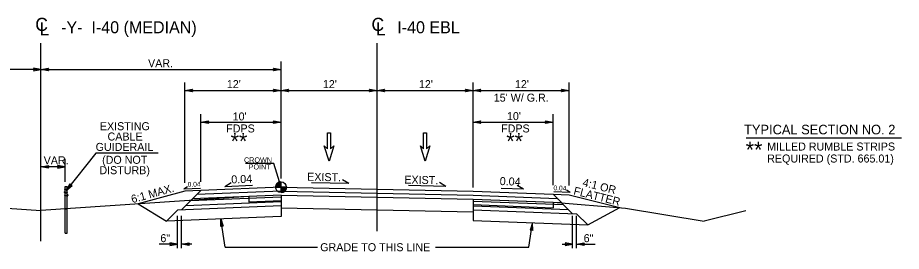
# Model space of a CAD drawing. Extents: x 1553195 to 1553792, y 810516 to 810787.
# Drawn here: x 1553280.5 to 1553390.9, y 810700.2 to 810729.4 of the extents above; entities that cross this region are included whole.
import ezdxf

# ---------------------------------------------------------------- set-up
doc = ezdxf.new("R2010")
doc.units = 0
for name, color, linetype in [('Old_Level_11', 7, 'Continuous'), ('Prop Dimension', 7, 'Continuous'), ('Prop DSN Text', 7, 'Continuous'), ('Prop Pavement Schedule Description CELL', 7, 'Continuous'), ('Prop Shade Light', 7, 'Continuous'), ('Prop Typical Section', 7, 'Continuous'), ('Sheet Sticker Incomplete CELL', 7, 'Continuous'), ('Typical Grade Point Symbol CELL', 7, 'Continuous'), ('Typical Pavement Slope CELL', 7, 'Continuous'), ('Typical Text Centerline CELL', 7, 'Continuous'), ('Typical Text Grade Point CELL', 7, 'Continuous'), ('Typical Text ID Circle CELL', 7, 'Continuous'), ('z - Construction', 7, 'Continuous')]:
    doc.layers.add(name, color=color, linetype=linetype)

msp = doc.modelspace()

# ---------------------------------------------------------------- linework, layer by layer
at = {"layer": 'Old_Level_11'}
for p, q in [((1553312.72, 810708.17), (1553313.39, 810708.17)), ((1553313.39, 810708.17), (1553313.39, 810708.84)), ((1553313.39, 810707.5), (1553313.39, 810708.17)), ((1553314.06, 810708.17), (1553313.39, 810708.17)), ((1553313.39, 810708.17), (1553313.39, 810707.5))]:
    msp.add_line(p, q, dxfattribs=at)
for points in [[(1553312.73, 810708.27), (1553312.73, 810708.17)], [(1553312.74, 810708.34), (1553312.74, 810708.17)], [(1553312.75, 810708.38), (1553312.75, 810708.17)], [(1553312.77, 810708.42), (1553312.77, 810708.17)], [(1553312.78, 810708.45), (1553312.78, 810708.17)], [(1553312.79, 810708.48), (1553312.79, 810708.17)], [(1553312.81, 810708.5), (1553312.81, 810708.17)], [(1553312.82, 810708.53), (1553312.82, 810708.17)], [(1553312.83, 810708.55), (1553312.83, 810708.17)], [(1553312.85, 810708.57), (1553312.85, 810708.17)], [(1553312.86, 810708.58), (1553312.86, 810708.17)], [(1553312.87, 810708.6), (1553312.87, 810708.17)], [(1553312.89, 810708.62), (1553312.89, 810708.17)], [(1553312.9, 810708.63), (1553312.9, 810708.17)], [(1553312.91, 810708.64), (1553312.91, 810708.17)], [(1553312.93, 810708.66), (1553312.93, 810708.17)], [(1553312.94, 810708.67), (1553312.94, 810708.17)], [(1553312.95, 810708.68), (1553312.95, 810708.17)], [(1553312.97, 810708.69), (1553312.97, 810708.17)], [(1553312.98, 810708.7), (1553312.98, 810708.17)], [(1553312.99, 810708.71), (1553312.99, 810708.17)], [(1553313.01, 810708.72), (1553313.01, 810708.17)], [(1553313.02, 810708.73), (1553313.02, 810708.17)], [(1553313.03, 810708.74), (1553313.03, 810708.17)], [(1553313.05, 810708.75), (1553313.05, 810708.17)], [(1553313.06, 810708.76), (1553313.06, 810708.17)], [(1553313.07, 810708.76), (1553313.07, 810708.17)], [(1553313.09, 810708.77), (1553313.09, 810708.17)], [(1553313.1, 810708.78), (1553313.1, 810708.17)], [(1553313.11, 810708.78), (1553313.11, 810708.17)], [(1553313.13, 810708.79), (1553313.13, 810708.17)], [(1553313.14, 810708.8), (1553313.14, 810708.17)], [(1553313.16, 810708.8), (1553313.16, 810708.17)], [(1553313.17, 810708.81), (1553313.17, 810708.17)], [(1553313.18, 810708.81), (1553313.18, 810708.17)], [(1553313.2, 810708.82), (1553313.2, 810708.17)], [(1553313.21, 810708.82), (1553313.21, 810708.17)], [(1553313.22, 810708.82), (1553313.22, 810708.17)], [(1553313.24, 810708.83), (1553313.24, 810708.17)], [(1553313.25, 810708.83), (1553313.25, 810708.17)], [(1553313.26, 810708.83), (1553313.26, 810708.17)], [(1553313.28, 810708.83), (1553313.28, 810708.17)], [(1553313.29, 810708.84), (1553313.29, 810708.17)], [(1553313.3, 810708.84), (1553313.3, 810708.17)], [(1553313.32, 810708.84), (1553313.32, 810708.17)], [(1553313.33, 810708.84), (1553313.33, 810708.17)], [(1553313.34, 810708.84), (1553313.34, 810708.17)], [(1553313.36, 810708.84), (1553313.36, 810708.17)], [(1553313.37, 810708.84), (1553313.37, 810708.17)], [(1553313.38, 810708.84), (1553313.38, 810708.84), (1553313.38, 810708.17)], [(1553313.4, 810708.17), (1553313.4, 810707.5), (1553313.4, 810707.5)], [(1553313.41, 810708.17), (1553313.41, 810707.5)], [(1553313.43, 810708.17), (1553313.43, 810707.5)], [(1553313.44, 810708.17), (1553313.44, 810707.5)], [(1553313.45, 810708.17), (1553313.45, 810707.5)], [(1553313.47, 810708.17), (1553313.47, 810707.51)], [(1553313.48, 810708.17), (1553313.48, 810707.51)], [(1553313.49, 810708.17), (1553313.49, 810707.51)], [(1553313.51, 810708.17), (1553313.51, 810707.51)], [(1553313.52, 810708.17), (1553313.52, 810707.51)], [(1553313.53, 810708.17), (1553313.53, 810707.52)], [(1553313.55, 810708.17), (1553313.55, 810707.52)], [(1553313.56, 810708.17), (1553313.56, 810707.52)], [(1553313.57, 810708.17), (1553313.57, 810707.53)], [(1553313.59, 810708.17), (1553313.59, 810707.53)], [(1553313.6, 810708.17), (1553313.6, 810707.53)], [(1553313.61, 810708.17), (1553313.61, 810707.54)], [(1553313.63, 810708.17), (1553313.63, 810707.54)], [(1553313.64, 810708.17), (1553313.64, 810707.55)], [(1553313.65, 810708.17), (1553313.65, 810707.56)], [(1553313.67, 810708.17), (1553313.67, 810707.56)], [(1553313.68, 810708.17), (1553313.68, 810707.57)], [(1553313.7, 810708.17), (1553313.7, 810707.57)], [(1553313.71, 810708.17), (1553313.71, 810707.58)], [(1553313.72, 810708.17), (1553313.72, 810707.59)], [(1553313.74, 810708.17), (1553313.74, 810707.6)], [(1553313.75, 810708.17), (1553313.75, 810707.61)], [(1553313.76, 810708.17), (1553313.76, 810707.61)], [(1553313.78, 810708.17), (1553313.78, 810707.62)], [(1553313.79, 810708.17), (1553313.79, 810707.63)], [(1553313.8, 810708.17), (1553313.8, 810707.64)], [(1553313.82, 810708.17), (1553313.82, 810707.65)], [(1553313.83, 810708.17), (1553313.83, 810707.66)], [(1553313.84, 810708.17), (1553313.84, 810707.68)], [(1553313.86, 810708.17), (1553313.86, 810707.69)], [(1553313.87, 810708.17), (1553313.87, 810707.7)], [(1553313.88, 810708.17), (1553313.88, 810707.72)], [(1553313.9, 810708.17), (1553313.9, 810707.73)], [(1553313.91, 810708.17), (1553313.91, 810707.75)], [(1553313.92, 810708.17), (1553313.92, 810707.76)], [(1553313.94, 810708.17), (1553313.94, 810707.78)], [(1553313.95, 810708.17), (1553313.95, 810707.8)], [(1553313.96, 810708.17), (1553313.96, 810707.82)], [(1553313.98, 810708.17), (1553313.98, 810707.85)], [(1553313.99, 810708.17), (1553313.99, 810707.87)], [(1553314, 810708.17), (1553314, 810707.9)], [(1553314.02, 810708.17), (1553314.02, 810707.93)], [(1553314.03, 810708.17), (1553314.03, 810707.97)], [(1553314.04, 810708.17), (1553314.04, 810708.02)], [(1553314.06, 810708.17), (1553314.06, 810708.1)]]:
    msp.add_lwpolyline(points, dxfattribs=at)
msp.add_circle((1553313.39, 810708.17), 0.671, dxfattribs=at)
for start, end in [(90.0095, 180.0095), (270.0095, 0.0095)]:
    msp.add_arc((1553313.39, 810708.17), 0.671, start, end, dxfattribs=at)
at = {"layer": 'Prop Dimension'}
for p, q in [((1553301.25, 810707.99), (1553301.71, 810708.28)), ((1553301.25, 810707.99), (1553303.32, 810708.07)), ((1553306.39, 810708.27), (1553307.16, 810708.76)), ((1553306.39, 810708.27), (1553309.84, 810708.41)), ((1553321.86, 810708.64), (1553317.2, 810708.73)), ((1553321.86, 810708.64), (1553321.07, 810709.11)), ((1553333.99, 810708.27), (1553329.33, 810708.37)), ((1553333.99, 810708.27), (1553333.2, 810708.75)), ((1553343.67, 810707.91), (1553340.88, 810708.02)), ((1553343.67, 810707.91), (1553342.9, 810708.4)), ((1553349.53, 810707.51), (1553347.46, 810707.59)), ((1553349.53, 810707.51), (1553349.07, 810707.8))]:
    msp.add_line(p, q, dxfattribs=at)
at = {"layer": 'Prop DSN Text'}
for points in [[(1553282.45, 810722.72), (1553283.39, 810722.88), (1553282.45, 810723.05), (1553282.57, 810722.88)], [(1553284.33, 810722.72), (1553283.39, 810722.88), (1553284.33, 810723.05), (1553284.21, 810722.88)], [(1553312.45, 810723.05), (1553313.39, 810722.88), (1553312.45, 810722.72), (1553312.57, 810722.88)], [(1553302.33, 810720.1), (1553301.39, 810720.26), (1553302.33, 810720.43), (1553302.21, 810720.26)], [(1553312.45, 810720.42), (1553313.39, 810720.26), (1553312.45, 810720.09), (1553312.57, 810720.26)], [(1553314.33, 810720.1), (1553313.39, 810720.26), (1553314.33, 810720.43), (1553314.21, 810720.26)], [(1553324.45, 810720.42), (1553325.39, 810720.26), (1553324.45, 810720.09), (1553324.57, 810720.26)], [(1553326.33, 810720.1), (1553325.39, 810720.26), (1553326.33, 810720.43), (1553326.21, 810720.26)], [(1553336.45, 810720.42), (1553337.39, 810720.26), (1553336.45, 810720.09), (1553336.57, 810720.26)], [(1553338.33, 810720.1), (1553337.39, 810720.26), (1553338.33, 810720.43), (1553338.21, 810720.26)], [(1553348.45, 810720.42), (1553349.39, 810720.26), (1553348.45, 810720.09), (1553348.57, 810720.26)], [(1553304.33, 810716.15), (1553303.39, 810716.31), (1553304.33, 810716.47), (1553304.21, 810716.31)], [(1553312.45, 810716.47), (1553313.39, 810716.31), (1553312.45, 810716.14), (1553312.57, 810716.31)], [(1553338.33, 810716.15), (1553337.39, 810716.31), (1553338.33, 810716.47), (1553338.21, 810716.31)], [(1553346.45, 810716.47), (1553347.39, 810716.31), (1553346.45, 810716.14), (1553346.57, 810716.31)], [(1553284.33, 810710.57), (1553283.39, 810710.73), (1553284.33, 810710.9), (1553284.21, 810710.73)], [(1553285.48, 810710.57), (1553286.41, 810710.73), (1553285.47, 810710.9), (1553285.59, 810710.73)], [(1553287.02, 810708.59), (1553286.57, 810707.76), (1553287.29, 810708.39), (1553287.08, 810708.4)], [(1553305.86, 810703.25), (1553305.88, 810704.2), (1553306.18, 810703.3), (1553306, 810703.39)], [(1553344.85, 810702.78), (1553344.83, 810703.73), (1553344.53, 810702.82), (1553344.71, 810702.91)], [(1553299.52, 810700.89), (1553300.46, 810701.05), (1553299.52, 810701.22), (1553299.64, 810701.05)], [(1553301.9, 810700.89), (1553300.96, 810701.05), (1553301.9, 810701.22), (1553301.78, 810701.05)], [(1553348.88, 810700.89), (1553349.82, 810701.05), (1553348.88, 810701.22), (1553349, 810701.05)], [(1553351.26, 810700.89), (1553350.32, 810701.05), (1553351.26, 810701.22), (1553351.14, 810701.05)]]:
    msp.add_lwpolyline(points, close=True, dxfattribs=at)
at = {"layer": 'Prop Pavement Schedule Description CELL'}
for p, q in [((1553349.39, 810708.4), (1553349.39, 810721.26)), ((1553347.39, 810708.41), (1553347.39, 810717.31)), ((1553371.49, 810714.36), (1553390.89, 810714.36)), ((1553306.41, 810700.67), (1553305.88, 810704.2)), ((1553344.37, 810700.67), (1553344.83, 810703.73)), ((1553306.41, 810700.67), (1553317.97, 810700.67)), ((1553332.69, 810700.67), (1553344.37, 810700.67))]:
    msp.add_line(p, q, dxfattribs=at)
at = {"layer": 'Prop Typical Section'}
for p, q in [((1553283.39, 810701.41), (1553283.39, 810726.17)), ((1553325.39, 810702.69), (1553325.39, 810726.17))]:
    msp.add_line(p, q, dxfattribs=at)
for points in [[(1553318.8, 810713.33), (1553319.2, 810712.96), (1553319.2, 810714.96), (1553319.58, 810714.96), (1553319.58, 810712.96), (1553319.98, 810713.33), (1553319.39, 810711.43)], [(1553318.8, 810713.33), (1553319.2, 810712.96), (1553319.2, 810714.96), (1553319.58, 810714.96), (1553319.58, 810712.96), (1553319.98, 810713.33), (1553319.39, 810711.43)], [(1553330.8, 810713.33), (1553331.2, 810712.96), (1553331.2, 810714.96), (1553331.58, 810714.96), (1553331.58, 810712.96), (1553331.98, 810713.33), (1553331.39, 810711.43)], [(1553330.8, 810713.33), (1553331.2, 810712.96), (1553331.2, 810714.96), (1553331.58, 810714.96), (1553331.58, 810712.96), (1553331.98, 810713.33), (1553331.39, 810711.43)]]:
    msp.add_lwpolyline(points, close=True, dxfattribs=at)
at = {"layer": 'Sheet Sticker Incomplete CELL'}
for p, q in [((1553301.39, 810707.69), (1553295.55, 810706.08)), ((1553303.39, 810707.77), (1553301.39, 810707.69)), ((1553347.39, 810707.29), (1553349.39, 810707.21)), ((1553349.39, 810707.21), (1553355.74, 810705.62)), ((1553295.55, 810706.08), (1553299.07, 810703.93)), ((1553351.71, 810703.45), (1553355.74, 810705.62))]:
    msp.add_line(p, q, dxfattribs=at)
at = {"layer": 'Typical Grade Point Symbol CELL'}
for p, q in [((1553257.39, 810707.01), (1553283.39, 810705.25)), ((1553309.39, 810707.01), (1553283.39, 810705.25)), ((1553313.39, 810707.17), (1553309.39, 810707.01)), ((1553309.39, 810707.01), (1553309.39, 810706.31)), ((1553313.39, 810707.17), (1553325.39, 810706.93)), ((1553313.39, 810707.17), (1553313.39, 810705.59)), ((1553325.39, 810706.93), (1553337.39, 810706.69)), ((1553313.39, 810706.47), (1553309.39, 810706.31)), ((1553337.39, 810706.69), (1553347.39, 810706.29)), ((1553337.39, 810706.69), (1553337.39, 810705.11)), ((1553337.39, 810705.99), (1553347.39, 810705.59)), ((1553347.39, 810706.29), (1553347.39, 810705.59)), ((1553347.39, 810706.29), (1553356.44, 810705.57)), ((1553313.39, 810705.59), (1553325.39, 810705.35)), ((1553325.39, 810705.35), (1553337.39, 810705.11)), ((1553356.44, 810705.57), (1553366.26, 810703.93)), ((1553371.47, 810705.23), (1553366.26, 810703.93))]:
    msp.add_line(p, q, dxfattribs=at)
at = {"layer": 'Typical Pavement Slope CELL'}
for p, q in [((1553313.39, 810708.17), (1553303.39, 810707.77)), ((1553313.39, 810708.17), (1553337.39, 810707.69)), ((1553303.39, 810707.77), (1553300.96, 810705.34)), ((1553313.39, 810706.92), (1553302.09, 810706.47)), ((1553313.39, 810707.17), (1553302.35, 810706.73)), ((1553313.39, 810707.67), (1553302.87, 810707.25)), ((1553313.39, 810707.67), (1553325.39, 810707.43)), ((1553325.39, 810707.43), (1553337.39, 810707.19)), ((1553337.39, 810707.69), (1553347.39, 810707.29)), ((1553337.39, 810707.19), (1553347.91, 810706.77)), ((1553347.39, 810707.29), (1553349.82, 810704.86)), ((1553313.39, 810705.84), (1553300.46, 810705.32)), ((1553313.39, 810706.34), (1553301.48, 810705.86)), ((1553337.39, 810706.69), (1553348.43, 810706.25)), ((1553337.39, 810706.44), (1553348.69, 810705.99)), ((1553337.39, 810705.86), (1553349.3, 810705.38)), ((1553300.46, 810705.32), (1553299.07, 810703.93)), ((1553313.39, 810705.59), (1553313.39, 810704.51)), ((1553337.39, 810705.36), (1553350.32, 810704.84)), ((1553337.39, 810705.11), (1553337.39, 810704.03)), ((1553350.32, 810704.84), (1553351.71, 810703.45)), ((1553313.39, 810704.51), (1553299.07, 810703.93)), ((1553337.39, 810704.03), (1553351.71, 810703.45))]:
    msp.add_line(p, q, dxfattribs=at)
at = {"layer": 'Typical Text Centerline CELL'}
for p, q in [((1553286.41, 810702.42), (1553286.41, 810708.25)), ((1553286.41, 810708.25), (1553286.66, 810708.25)), ((1553286.66, 810702.42), (1553286.66, 810708.25)), ((1553286.67, 810708.01), (1553286.67, 810708.04)), ((1553286.67, 810708.04), (1553286.7, 810708.04)), ((1553286.38, 810707.88), (1553286.38, 810707.91)), ((1553286.38, 810707.91), (1553286.7, 810707.91)), ((1553286.7, 810707.88), (1553286.38, 810707.88)), ((1553286.41, 810707.64), (1553286.38, 810707.64)), ((1553286.38, 810707.62), (1553286.41, 810707.62)), ((1553286.7, 810707.51), (1553286.38, 810707.51)), ((1553286.38, 810707.49), (1553286.7, 810707.49)), ((1553286.38, 810707.09), (1553286.38, 810707.12)), ((1553286.38, 810707.12), (1553286.7, 810707.12)), ((1553286.7, 810707.09), (1553286.38, 810707.09)), ((1553286.41, 810707.62), (1553286.41, 810707.64)), ((1553286.7, 810708.01), (1553286.67, 810708.01)), ((1553286.67, 810707.22), (1553286.67, 810707.25)), ((1553286.67, 810707.25), (1553286.7, 810707.25)), ((1553286.7, 810707.22), (1553286.67, 810707.22)), ((1553286.7, 810707.49), (1553286.7, 810707.51)), ((1553286.41, 810702.42), (1553286.66, 810702.42))]:
    msp.add_line(p, q, dxfattribs=at)
for centre in [(1553286.37, 810707.56), (1553286.71, 810707.96), (1553286.71, 810707.17)]:
    msp.add_circle(centre, 0.0416, dxfattribs=at)
for centre, radius, start, end in [((1553286.7, 810707.96), 0.0781, 270, 90), ((1553286.38, 810707.56), 0.0781, 90, 270), ((1553286.38, 810707.56), 0.0521, 90, 270), ((1553286.7, 810707.96), 0.0521, 270, 90), ((1553286.7, 810707.17), 0.0781, 270, 90), ((1553286.7, 810707.17), 0.0521, 270, 90)]:
    msp.add_arc(centre, radius, start, end, dxfattribs=at)
at = {"layer": 'Typical Text Grade Point CELL'}
msp.add_line((1553286.41, 810705.46), (1553286.66, 810705.46), dxfattribs=at)
at = {"layer": 'Typical Text ID Circle CELL'}
msp.add_lwpolyline([(1553313.39, 810708.17), (1553312.49, 810711.13), (1553308.95, 810711.13)], dxfattribs=at)
at = {"layer": 'z - Construction'}
for p, q in [((1553313.39, 810709.28), (1553313.39, 810723.88)), ((1553283.39, 810722.88), (1553253.39, 810722.88)), ((1553283.39, 810722.88), (1553313.39, 810722.88)), ((1553301.39, 810708.74), (1553301.39, 810721.26)), ((1553301.39, 810720.26), (1553313.39, 810720.26)), ((1553313.39, 810720.26), (1553325.39, 810720.26)), ((1553325.39, 810720.26), (1553337.39, 810720.26)), ((1553337.39, 810708.14), (1553337.39, 810721.26)), ((1553337.39, 810720.26), (1553349.39, 810720.26)), ((1553303.39, 810708.86), (1553303.39, 810717.31)), ((1553303.39, 810716.31), (1553313.39, 810716.31)), ((1553337.39, 810716.31), (1553347.39, 810716.31)), ((1553286.41, 810708.84), (1553286.41, 810711.73)), ((1553286.41, 810710.73), (1553283.39, 810710.73)), ((1553300.46, 810700.57), (1553300.46, 810704.58)), ((1553300.96, 810700.57), (1553300.96, 810704.58)), ((1553349.82, 810700.57), (1553349.82, 810704.58)), ((1553350.32, 810700.57), (1553350.32, 810704.58)), ((1553300.46, 810701.05), (1553298.16, 810701.05)), ((1553302.25, 810701.05), (1553300.96, 810701.05)), ((1553348.53, 810701.05), (1553349.82, 810701.05)), ((1553350.32, 810701.05), (1553352.62, 810701.05))]:
    msp.add_line(p, q, dxfattribs=at)
msp.add_lwpolyline([(1553298.06, 810712.41), (1553290.25, 810712.41), (1553286.57, 810707.76)], dxfattribs=at)

# ---------------------------------------------------------------- texts
at = {"layer": 'Prop Pavement Schedule Description CELL'}
for s, height, p in [('-Y-  I-40 (MEDIAN)', 1.5, (1553285.92, 810727.42)), ('I-40 EBL', 1.5, (1553327.92, 810727.42)), ('VAR.', 1, (1553296.78, 810723.18)), ("12'", 1, (1553306.62, 810720.56)), ("12'", 1, (1553318.62, 810720.56)), ("12'", 1, (1553330.62, 810720.56)), ("12'", 1, (1553342.62, 810720.56)), ("15' W/ G.R.", 1, (1553339.97, 810718.87)), ("10'", 1, (1553307.35, 810716.52)), ("10'", 1, (1553341.62, 810716.56)), ('EXISTING', 1, (1553290.76, 810715.3)), ('FDPS', 1, (1553306.54, 810715.02)), ('FDPS', 1, (1553340.89, 810715.02)), ('TYPICAL SECTION NO. 2', 1.2, (1553371.24, 810714.78)), ('CABLE', 1, (1553291.72, 810714.01)), ('**', 2, (1553307.1, 810712.93)), ('**', 2, (1553341.54, 810712.93)), ('GUIDERAIL', 1, (1553290.23, 810712.71)), ('**', 2, (1553371.45, 810711.86)), ('MILLED RUMBLE STRIPS', 1, (1553374.13, 810712.76)), ('VAR.', 1, (1553283.74, 810711.03)), ('(DO NOT', 1, (1553291.04, 810711.1)), ('REQUIRED (STD. 665.01)', 1, (1553374.13, 810711.26)), ('DISTURB)', 1, (1553290.7, 810709.8)), ('6"', 1, (1553298.32, 810701.3)), ('6"', 1, (1553351.2, 810701.3)), ('GRADE TO THIS LINE', 1, (1553318.29, 810700.17))]:
    msp.add_text(s, height=height, dxfattribs=at).set_placement(p)
for s, height, rotation, p in [('0.04', 1, 2.2906, (1553307.2, 810708.64)), ('EXIST.', 1, 358.8541, (1553316.65, 810708.99)), ('EXIST.', 1, 358.8541, (1553328.79, 810708.63)), ('0.04', 1, 357.7094, (1553340.7, 810708.45)), ('4:1 OR', 1, 345.9638, (1553351, 810708.33)), ('6:1 MAX.', 1, 15.4677, (1553294.82, 810706.17)), ('0.04', 0.6, 2.2906, (1553301.74, 810708.21)), ('0.04', 0.6, 357.7094, (1553347.42, 810707.8)), ('FLATTER', 1, 345.9638, (1553349.87, 810707.28))]:
    msp.add_text(s, height=height, rotation=rotation, dxfattribs=at).set_placement(p)
at = {"layer": 'Prop Shade Light'}
for p in [(1553282.69, 810727.71), (1553324.69, 810727.71)]:
    msp.add_text('C', height=1.64, dxfattribs=at).set_placement(p)
for p in [(1553283.23, 810727.15), (1553325.23, 810727.15)]:
    msp.add_text('L', height=1.64, rotation=359.9469, dxfattribs=at).set_placement(p)
at = {"layer": 'Typical Text Grade Point CELL'}
msp.add_text('GROUND LINE', height=0.01, dxfattribs=at).set_placement((1553286.48, 810705.46))
at = {"layer": 'Typical Text ID Circle CELL'}
for s, p in [('CROWN', (1553308.77, 810711.25)), ('POINT', (1553309.35, 810710.39))]:
    msp.add_text(s, height=0.652, dxfattribs=at).set_placement(p)

doc.saveas('drawing.dxf')
